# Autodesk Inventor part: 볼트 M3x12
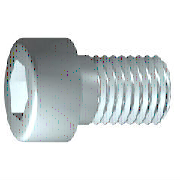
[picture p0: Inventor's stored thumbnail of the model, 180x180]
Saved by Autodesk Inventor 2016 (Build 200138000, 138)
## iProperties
IsCustomPart: 0
Created: 2012-02
Part Number: 볼트 M3x12
Material: 강철, 연강
Description: 6각머리 태핑 나사
Document SubType Name: Modeling
Standard: KS B 1003
Designer: mduedu
Standards Organization: KS
Language: ko-KR
Size Designation: M 3 x 12
Categories: <MemberInstance><Categories><Category DisplayName="조임쇠" InternalName="e4da775c-781d-43d5-af7c-5136215cf5a6" Mnemonic="FSTN"><Category DisplayName="볼트" InternalN
Density: 7.85 g/cm^3
Appearance: 강철
Mass: 1.15061 g
Surface Area: 2.207 cm^2
Volume: 0.146575 cm^3
Author: mduedu
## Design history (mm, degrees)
sketch "스케치1"
  geometry: L1 (-0.867, 0)-(12, 0); L2 (12, 0)-(12, 1.5); L3 (12, 1.5)-(1.25, 1.5); L4 (1.25, 1.5)-(0.943, 1.5); L5 (0.943, 1.5)-(0, 1.5); L6 (0, 1.5)-(0, 2.75); L7 (0, 2.75)-(-3, 2.75); L8 (-3, 2.75)-(-3, 1.443); L9 (-3, 1.443)-(-1.7, 1.443); L10 (-1.7, 1.443)-(-0.867, 0); L11 (-6, 0)-(15, 0) reference; L12 (0, -0.55)-(0, 3.3) reference; L13 (1.25, 1.5)-(0, 1.5)
  constraints: 22 end point, 6 parallel, 2 collinear, 2 perpendicular, 1 horizontal, 1 point on line
  dimensions: "d1" = 10.75 distance from line of L3.end L2 (= GEL); "d2" = 0.30683 distance of L4.end L3.end (computed from GAL); "d3" = 3 distance between parallel lines of L8 L6 (= KOH); "d4" = 1.3 distance of L8.end L9.end (= INTI); "d5" = 60 deg angle of L10 L1; "d6" = 3 diameter of L3 L1 (= GD); "d7" = 3 diameter of L5 L1 (= BDM); "d8" = 2.88675 diameter of L9 L1 (= 1.1547 x SW); "d9" = 5.5 diameter of L7 L1 (= KOD); "d26" = 12 distance between parallel lines of L12 L2 (= NLG)
revolve "본체" sketch "스케치1" stored, may be unused: angle "d10" = 90 deg
sketch "스케치2"
  geometry: L1 (0, -3.85)-(0, 3.85) reference; L2 (-3.85, 0)-(3.85, 0) reference; L3 (1.443, 0)-(0.722, -1.25); L4 (0.722, -1.25)-(-0.722, -1.25); L5 (-0.722, -1.25)-(-1.443, 0); L6 (-1.443, 0)-(-0.722, 1.25); L7 (-0.722, 1.25)-(0.722, 1.25); L8 (0.722, 1.25)-(1.443, 0); 2 further points
  constraints: 12 end point, 1 coincident, 1 horizontal alignment, 1 point on line, 12 other
extrude "슬롯" join sketch "스케치2" stored distance "d11" = 10; taper "d12" = 0 deg
workplane "Work Plane1"
fillet "Fillet2" dims "d30" = 0.1 (= R)
body "Solid1"
fillet "모깎기1" dims "d17" = 0.3 (= RR)
feature "스레드" dims "d13" = 10.75 (= GEL), "d14" = 0
chamfer "모따기1" distance "d15" = 0.30673 (= -0.5 x SPD + 0.5 x GD); stored, may be unused: second distance "d16" = 0.30673 (= GUL), angle "d27" = 45 deg
other parameters: "GD" = 3 (= NND) [user parameter; used in 2 equation terms], "NLG" = 12 [user parameter; used in 1 equation term], "GEL" = 10.75 [user parameter; used in 2 equation terms], "KOD" = 5.5 [user parameter; used in 1 equation term], "KOH" = 3 [user parameter; used in 1 equation term], "INTI" = 1.3 [user parameter; used in 1 equation term], "GAL" = 0.30673 (= 0.61345 x PTC) [user parameter; used in 1 equation term], "GUL" = 0.30673 (= 0.61345 x PTC) [user parameter; used in 1 equation term], "BDM" = 3 (= NND) [user parameter; used in 1 equation term], "SW" = 2.5 [user parameter; used in 2 equation terms], "RR" = 0.3 [user parameter; used in 1 equation term], "SPD" = 2.38655 (= NND - 1.2269 x PTC) [user parameter; used in 1 equation term], "d19" = 0, "d28" = 0, "d29" = 0, "R" = 0.1 [user parameter; used in 1 equation term], "PHH" = 0.1 [user parameter], "GD1" = 2.38655 (= THREADDIA - 1.2269 x PTC) [user parameter], "THREADDIA" = 3 [user parameter; used in 1 equation term], "FAWI" = 45 deg [user parameter], "PTC" = 0.5 [user parameter; used in 5 equation terms], "NND" = 3 [user parameter; used in 3 equation terms], "TOA" = 30 deg [user parameter], "E0" = 2.8875 (= 1.155 x SW) [user parameter]
